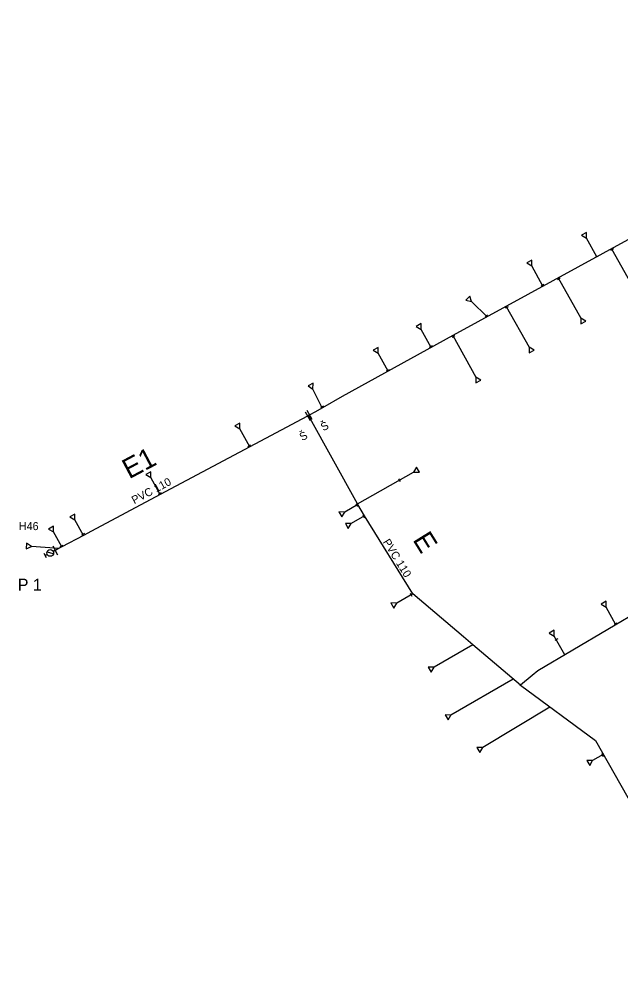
# Model space of a CAD drawing. Extents: x -574467 to -573664, y -1191210 to -1190404.
# Drawn here: x -574245.7 to -574095.2, y -1190717.5 to -1190478.9 of the extents above; entities that cross this region are included whole.
import ezdxf

# ---------------------------------------------------------------- set-up
doc = ezdxf.new("R2010")
doc.units = 0
for name, color, linetype in [('Vrstva 1', 7, 'Continuous'), ('Vrstva 12', 7, 'Continuous'), ('Vrstva 15', 7, 'Continuous'), ('Vrstva 25', 7, 'Continuous'), ('Vrstva 28', 7, 'Continuous'), ('Vrstva 29', 7, 'Continuous'), ('Vrstva 35', 7, 'Continuous')]:
    doc.layers.add(name, color=color, linetype=linetype)

# ---------------------------------------------------------------- blocks, each defined once
blk = doc.blocks.new('160')
at = {"layer": 'Vrstva 1'}
blk.add_circle((0, 0), 0.0458, dxfattribs=at)
blk = doc.blocks.new('147')
at = {"layer": 'Vrstva 1'}
blk.add_line((0, 1.27), (0, -1.27), dxfattribs=at)
blk = doc.blocks.new('133')
at = {"layer": 'Vrstva 1'}
for p, q in [((0.28, 0), (0, 0)), ((0.54, 0.58), (1.7, -0.58)), ((1.94, 0), (2.52, 0)), ((2.52, 0.58), (2.52, -0.58))]:
    blk.add_line(p, q, dxfattribs=at)
blk.add_circle((1.105, 0.003), 0.825, dxfattribs=at)
blk = doc.blocks.new('150')
at = {"layer": 'Vrstva 1'}
blk.add_line((0, 1.27), (0, -1.27), dxfattribs=at)
blk = doc.blocks.new('151')
at = {"layer": 'Vrstva 1'}
blk.add_line((0, 0.4), (0, -0.4), dxfattribs=at)
blk = doc.blocks.new('130')
at = {"layer": 'Vrstva 1'}
for p, q in [((1.25, 0.72), (0, 0)), ((0, 0), (1.25, -0.72)), ((1.25, -0.72), (1.25, 0.72))]:
    blk.add_line(p, q, dxfattribs=at)

msp = doc.modelspace()

# ---------------------------------------------------------------- linework, layer by layer
at = {"layer": 'Vrstva 12'}
for p, q in [((-574101.277, -1190538.306), (-574103.83, -1190533.658)), ((-574097.585, -1190536.287), (-574092.021, -1190546.188)), ((-574114.717, -1190545.657), (-574117.539, -1190540.553)), ((-574110.888, -1190543.563), (-574105.241, -1190553.617)), ((-574128.661, -1190553.284), (-574132.583, -1190549.498)), ((-574123.929, -1190550.696), (-574118.158, -1190560.889)), ((-574142.663, -1190560.974), (-574145.161, -1190556.432)), ((-574137.249, -1190557.982), (-574131.457, -1190568.381)), ((-574153.415, -1190566.918), (-574155.93, -1190562.401)), ((-574169.868, -1190576.012), (-574172.217, -1190571.352)), ((-574188.003, -1190585.83), (-574190.481, -1190581.299)), ((-574161.062, -1190600.067), (-574147.062, -1190592.084)), ((-574210.395, -1190597.735), (-574212.762, -1190593.461)), ((-574160.982, -1190600.205), (-574164.266, -1190602.076)), ((-574229.563, -1190607.907), (-574231.722, -1190604.051)), ((-574159.345, -1190603.043), (-574162.641, -1190604.926)), ((-574234.992, -1190610.788), (-574237.087, -1190607.069)), ((-574235.704, -1190611.166), (-574242.58, -1190610.66)), ((-574147.266, -1190622.491), (-574151.274, -1190624.824)), ((-574096.465, -1190630.242), (-574098.908, -1190625.84)), ((-574109.264, -1190637.788), (-574111.903, -1190633.071)), ((-574132.27, -1190635.248), (-574141.938, -1190640.836)), ((-574122.149, -1190643.858), (-574137.714, -1190652.807)), ((-574112.97, -1190650.826), (-574129.774, -1190660.901)), ((-574099.645, -1190662.663), (-574102.301, -1190664.192))]:
    msp.add_line(p, q, dxfattribs=at)
at = {"layer": 'Vrstva 15'}
for p, q in [((-574173.286, -1190577.983), (-574173.546, -1190578.132)), ((-574173.02, -1190577.83), (-574173.286, -1190577.983))]:
    msp.add_line(p, q, dxfattribs=at)
for points in [[(-574011.808, -1190478.895), (-574022.069, -1190486.647), (-574034.639, -1190496.364), (-574043.695, -1190502.866), (-574050.388, -1190507.493), (-574071.014, -1190521.753), (-574081.02, -1190527.226), (-574137.249, -1190557.982), (-574164.872, -1190573.251), (-574169.864, -1190576.01), (-574171.768, -1190577.11), (-574173.02, -1190577.83)], [(-573951.945, -1190547.448), (-573966.611, -1190556.618), (-573976.732, -1190562.193), (-573991.762, -1190570.848), (-573993.455, -1190571.823), (-574006.385, -1190578.776), (-574012.553, -1190582.093), (-574020.568, -1190587.019), (-574022.653, -1190588.301), (-574026.786, -1190590.606), (-574030.918, -1190592.912), (-574051.57, -1190604.003), (-574065.696, -1190612.425), (-574079.8, -1190620.445), (-574081.027, -1190621.142), (-574115.994, -1190641.755), (-574117.43, -1190642.95), (-574120.356, -1190645.383)], [(-574173.546, -1190578.132), (-574174.968, -1190578.9), (-574180.134, -1190581.647), (-574210.395, -1190597.735), (-574227.566, -1190606.847), (-574229.563, -1190607.907), (-574234.992, -1190610.788), (-574236.416, -1190611.544), (-574236.572, -1190611.627)], [(-574120.356, -1190645.383), (-574132.27, -1190635.248), (-574134.61, -1190633.257), (-574147.266, -1190622.491), (-574159.345, -1190603.043), (-574160.982, -1190600.205), (-574161.062, -1190600.067), (-574173.286, -1190577.983)], [(-574120.356, -1190645.383), (-574101.615, -1190659.194), (-574068.493, -1190717.509)]]:
    msp.add_lwpolyline(points, dxfattribs=at)
at = {"layer": 'Vrstva 25'}
msp.add_line((-574236.572, -1190611.627), (-574236.88, -1190611.79), dxfattribs=at)

# ---------------------------------------------------------------- block references
at = {"layer": 'Vrstva 12'}
for name, p, xscale, yscale, rotation in [('130', (-574103.83, -1190533.658), 0.999999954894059, 0.9999999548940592, 119.00000058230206), ('151', (-574101.277, -1190538.306), 0.9999999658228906, 0.9999999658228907, -62.00000017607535), ('151', (-574097.456, -1190536.517), 0.9999999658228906, 0.9999999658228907, -62.00000017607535), ('130', (-574117.539, -1190540.553), 0.999999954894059, 0.9999999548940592, 119.00000058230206), ('151', (-574114.842, -1190545.43), 0.9999999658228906, 0.9999999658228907, -62.00000017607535), ('151', (-574110.731, -1190543.843), 0.9999999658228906, 0.9999999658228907, -62.00000017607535), ('130', (-574132.583, -1190549.498), 0.9999999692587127, 0.9999999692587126, 136.00000080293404), ('151', (-574123.781, -1190550.957), 0.999999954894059, 0.9999999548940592, -60.999999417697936), ('130', (-574145.161, -1190556.432), 0.999999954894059, 0.9999999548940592, 119.00000058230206), ('151', (-574128.845, -1190553.107), 0.999999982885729, 0.9999999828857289, -45), ('130', (-574105.241, -1190553.617), 0.9999999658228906, 0.9999999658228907, -62.00000017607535), ('151', (-574137.1, -1190558.249), 0.9999999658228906, 0.9999999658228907, -62.00000017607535), ('130', (-574155.93, -1190562.401), 0.999999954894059, 0.9999999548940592, 119.00000058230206), ('151', (-574142.778, -1190560.764), 0.9999999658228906, 0.9999999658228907, -62.00000017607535), ('130', (-574118.158, -1190560.889), 0.999999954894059, 0.9999999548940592, -60.999999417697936), ('151', (-574153.536, -1190566.701), 0.9999999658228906, 0.9999999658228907, -62.00000017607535), ('130', (-574131.457, -1190568.381), 0.9999999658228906, 0.9999999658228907, -62.00000017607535), ('130', (-574172.217, -1190571.352), 0.999999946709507, 0.999999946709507, 117.00000088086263), ('151', (-574169.963, -1190575.824), 0.9999999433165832, 0.999999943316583, -64.0000000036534), ('130', (-574190.481, -1190581.299), 0.999999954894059, 0.9999999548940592, 119.00000058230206), ('151', (-574188.137, -1190585.585), 0.9999999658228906, 0.9999999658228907, -62.00000017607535), ('130', (-574212.762, -1190593.461), 0.999999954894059, 0.9999999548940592, 119.00000058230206), ('130', (-574147.062, -1190592.084), 0.9999999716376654, 0.9999999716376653, 29.999998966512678), ('151', (-574150.6, -1190594.101), 0.9999999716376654, 0.9999999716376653, 29.999998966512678), ('151', (-574210.539, -1190597.476), 0.9999999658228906, 0.9999999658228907, -62.00000017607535), ('151', (-574161.3, -1190600.386), 0.9999999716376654, 0.9999999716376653, 29.999998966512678), ('130', (-574231.722, -1190604.051), 0.999999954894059, 0.9999999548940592, 119.00000058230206), ('130', (-574164.266, -1190602.076), 1.0037041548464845, 1.0037041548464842, -150.62079141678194), ('130', (-574162.641, -1190604.926), 1.0037041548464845, 1.0037041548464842, -150.62079141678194), ('151', (-574159.557, -1190603.164), 0.9999999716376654, 0.9999999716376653, 29.999998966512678), ('130', (-574237.087, -1190607.069), 0.999999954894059, 0.9999999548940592, 119.00000058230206), ('151', (-574229.707, -1190607.649), 0.9999999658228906, 0.9999999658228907, -62.00000017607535), ('130', (-574242.58, -1190610.66), 0.9999999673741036, 0.9999999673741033, 176.00000004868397), ('151', (-574235.094, -1190610.606), 0.9999999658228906, 0.9999999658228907, -62.00000017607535), ('130', (-574151.274, -1190624.824), 1.0037041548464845, 1.0037041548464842, -150.62079141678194), ('151', (-574147.671, -1190622.727), 0.9999999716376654, 0.9999999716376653, 29.999998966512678), ('130', (-574098.908, -1190625.84), 0.999999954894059, 0.9999999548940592, 119.00000058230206), ('151', (-574096.579, -1190630.037), 0.9999999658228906, 0.9999999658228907, -62.00000017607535), ('130', (-574111.903, -1190633.071), 0.999999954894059, 0.9999999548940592, 119.00000058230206), ('151', (-574111.392, -1190633.984), 0.9999999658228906, 0.9999999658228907, -62.00000017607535), ('130', (-574141.938, -1190640.836), 1.0037041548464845, 1.0037041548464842, -150.62079141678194), ('130', (-574137.714, -1190652.807), 1.0037041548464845, 1.0037041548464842, -150.62079141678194), ('130', (-574129.774, -1190660.901), 0.9999999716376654, 0.9999999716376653, -150.00000103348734), ('130', (-574102.301, -1190664.192), 1.0037041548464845, 1.0037041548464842, -150.62079141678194), ('151', (-574099.866, -1190662.79), 0.9999999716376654, 0.9999999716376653, 29.999998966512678)]:
    msp.add_blockref(name, p, dxfattribs=dict(at, xscale=xscale, yscale=yscale, rotation=rotation))
at = {"layer": 'Vrstva 25'}
for name, p, xscale, yscale, rotation in [('133', (-574236.88, -1190611.79), 1.0106517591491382, 1.010651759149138, -151.83788415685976), ('150', (-574236.647, -1190611.666), 1.0072562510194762, 1.0072562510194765, 28.766663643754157)]:
    msp.add_blockref(name, p, dxfattribs=dict(at, xscale=xscale, yscale=yscale, rotation=rotation))
at = {"layer": 'Vrstva 29'}
for name, p, xscale, yscale, rotation in [('147', (-574173.546, -1190578.132), 1.0037041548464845, 1.0037041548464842, 29.379208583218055), ('147', (-574173.02, -1190577.83), 1.0037041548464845, 1.0037041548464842, -150.62079141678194), ('160', (-574173.286, -1190577.983), 0.9999999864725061, 0.9999999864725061, 74.0000013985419), ('160', (-574236.572, -1190611.627), 1.0106517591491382, 1.010651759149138, -151.83788415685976), ('160', (-574120.356, -1190645.383), 0.9999999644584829, 0.999999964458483, -39.000001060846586)]:
    msp.add_blockref(name, p, dxfattribs=dict(at, xscale=xscale, yscale=yscale, rotation=rotation))

# ---------------------------------------------------------------- texts
at = {"layer": 'Vrstva 25'}
for s, height, p in [('H46', 2, (-574245.7, -1190606.6)), ('P 1', 3, (-574245.99, -1190621.75))]:
    msp.add_text(s, height=height, dxfattribs=at).set_placement(p)
at = {"layer": 'Vrstva 28'}
for rotation, p in [(29.39, (-574169.596, -1190581.921)), (29.6, (-574174.883, -1190584.394))]:
    msp.add_text('Š', height=2, rotation=rotation, dxfattribs=at).set_placement(p)
at = {"layer": 'Vrstva 35'}
for s, height, rotation, p in [('E1', 5, 27.95, (-574218.152, -1190593.927)), ('PVC 110', 2, 27.95, (-574216.874, -1190600.159)), ('E', 5, 301.84, (-574147.398, -1190609.001)), ('PVC 110', 2, 301.84, (-574154.822, -1190609.564))]:
    msp.add_text(s, height=height, rotation=rotation, dxfattribs=at).set_placement(p)

doc.saveas('drawing.dxf')
